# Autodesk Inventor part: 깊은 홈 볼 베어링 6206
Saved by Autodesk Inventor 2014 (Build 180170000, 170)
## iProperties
Created: 2025-06
Part Number: 깊은 홈 볼 베어링 6206
Material: 일반
Document SubType Name: Modeling
Designer: dg
Density: 1 g/cm^3
Appearance: 기본값
Author: dg
Author: jhkim
Description: 깊은 그루부 볼 베어링
Creation Date: 2025-05-23
Sending System: Autodesk Inventor 2026
Preprocessor: ST-DEVELOPER v20.1
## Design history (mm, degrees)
node "깊은 홈 볼 베어링 62061"
body "Solid1"
node "Solid1_1"
node "Solid1_2"
node "Solid1_3"
node "Solid1_4"
node "Solid1_5"
node "Solid1_6"
node "Solid1_7"
node "Solid1_8"
node "Solid1_9"
node "Solid1_10"
node "기준1"
node "기준2"
node "기준3"
node "기준4"
node "기준5"
node "기준6"
node "기준7"
node "기준8"
node "기준9"
node "기준10"
node "기준11"
